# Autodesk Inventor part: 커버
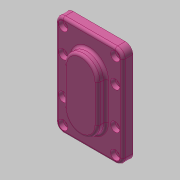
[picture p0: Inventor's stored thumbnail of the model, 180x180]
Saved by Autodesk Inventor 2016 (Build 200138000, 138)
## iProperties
Created: 2019-03
Part Number: 커버
Material: 알루미늄 6061
Document SubType Name: Modeling
Designer: mduedu
Density: 1 g/cm^3
Appearance: 분홍색
Author: mduedu
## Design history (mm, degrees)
sketch "스케치1"
  geometry: L1 (-60, 40)-(60, 40); L2 (60, 40)-(60, -40); L3 (60, -40)-(-60, -40); L4 (-60, -40)-(-60, 40); L5 (-60, 40)-(60, -40); L6 (60, 40)-(-60, -40); 1 further point
  constraints: 12 end point, 2 midpoint, 2 parallel, 1 horizontal, 1 perpendicular
  dimensions: "d59" = 120 distance of L2.end L3.end; "d60" = 80 distance of L1.end L2.end
extrude "돌출1" new body sketch "스케치1" distance "d4" = 12; taper "d5" = 0 deg
sketch "스케치2"
  geometry: L1 (-20, -22)-(20, -22); L2 (20, -22)-(20, 22); L3 (20, 22)-(-20, 22); L4 (-20, 22)-(-20, -22); L5 (-20, -22)-(20, 22); L6 (20, -22)-(-20, 22); 3 further points
  constraints: 12 end point, 4 midpoint, 2 horizontal alignment, 2 parallel, 1 horizontal, 1 perpendicular, 4 other
  dimensions: "d6" = 40 distance between parallel lines of L2 L4; "d8" = 44 distance between parallel lines of L1 L3
extrude "돌출2" join sketch "스케치2" distance "d9" = 10; taper "d10" = 0 deg
fillet "모깎기1" dims "d11" = 9
fillet "모깎기2" dims "d12" = 3
sketch "스케치3"
  geometry: L1 (-31, -60)-(31, -60) reference; L2 (-40, 51)-(-40, -51) reference; L3 (31, 60)-(-31, 60) reference; L4 (40, -51)-(40, 51) reference; L5 (-17, -22)-(-17, 22) reference; L6 (17, 22)-(17, -22) reference; L7 (-31, 51)-(31, 51); L8 (31, 51)-(31, -51); L9 (31, -51)-(-31, -51); L10 (-31, -51)-(-31, 51); A1 r 9 centre (31, -51) between (31, -60) and (40, -51) reference; A2 r 9 centre (-31, -51) between (-40, -51) and (-31, -60) reference; A3 r 9 centre (-31, 51) between (-31, 60) and (-40, 51) reference; A4 r 9 centre (31, 51) between (40, 51) and (31, 60) reference; A5 r 17 centre (0, -22) between (-17, -22) and (17, -22) reference; A6 r 17 centre (0, 22) between (17, 22) and (-17, 22) reference; 9 further points
  constraints: 8 end point, 4 coincident, 4 horizontal alignment, 4 point on line, 2 parallel, 1 horizontal, 1 perpendicular
hole "구멍2" sketch "스케치3" at (-31, 51), (31, 51), (31, -51), (-31, -51), (-31, 22), (-31, -22), (31, 22), (31, -22) diameter "d28" = 5.5; stored, may be unused: countersink angle "d32" = 90 deg, drill point angle "d34" = 118 deg; dims "d29" = 6, "d30" = 4, "d31" = 2, "d33" = 8
sketch "스케치9"
  geometry: L1 (40, -51)-(40, 51) reference; L2 (31, 60)-(-31, 60) reference; L3 (-40, 51)-(-40, -51) reference; L4 (-31, -60)-(31, -60) reference; L5 (23, -22)-(23, 22) reference; L6 (-23, 22)-(-23, -22) reference; C1 r 2.75 at (31, 22) reference; C2 r 2.75 at (-31, 22) reference; C3 r 2.75 at (31, -51) reference; C4 r 2.75 at (-31, 51) reference; C5 r 2.75 at (31, 51) reference; C6 r 2.75 at (-31, -51) reference; C7 r 2.75 at (-31, -22) reference; C8 r 2.75 at (31, -22) reference; A1 r 9 centre (31, -51) between (31, -60) and (40, -51) reference; A2 r 9 centre (31, 51) between (40, 51) and (31, 60) reference; A3 r 9 centre (-31, 51) between (-31, 60) and (-40, 51) reference; A4 r 9 centre (-31, -51) between (-40, -51) and (-31, -60) reference; A5 r 23 centre (0, -22) between (-23, -22) and (23, -22) reference; A6 r 23 centre (0, 22) between (23, 22) and (-23, 22) reference; 9 further points
  constraints: 8 coincident
hole "구멍4" sketch "스케치9" at (-31, 51), (31, 51), (31, 22), (-31, 22), (-31, -22), (31, -22), (31, -51), (-31, -51) diameter "d69" = 11; stored, may be unused: countersink angle "d73" = 90 deg, drill point angle "d75" = 0 deg; dims "d70" = 6, "d71" = 4, "d72" = 2, "d74" = 5.4
fillet "모깎기3" dims "d68" = 3
sketch "스케치6"
  geometry: C1 r 12.5 at (0, 22); 1 further point
  constraints: 1 centre point, 1 vertical alignment
  dimensions: "d43" = 25 diameter of C1; "d45" = 22 distance of C1.centre point (0, 0)
extrude "돌출5" cut sketch "스케치6" distance "d47" = 15; taper "d48" = 0 deg
node "솔리드1"
mirror "대칭1"
node "투영된 루프2"
node "투영된 루프3"
node "투영된 루프4"
